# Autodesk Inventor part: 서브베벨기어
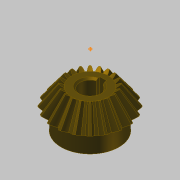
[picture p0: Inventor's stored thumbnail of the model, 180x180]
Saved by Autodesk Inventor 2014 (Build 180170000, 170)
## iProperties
Created: 2018-09
Part Number: 서브베벨기어
Material: 강철, 탄소
Document SubType Name: Modeling
Categories: <?xml version="1.0" encoding="UTF-16"?> <MemberInstance><Categories><FamilyTemplate><FamilyTemplateParameter ValueType="xs:double" Id="1" ObjectReferenceKey="da
Mass: 135.037 g
Surface Area: 63.6444 cm^2
Volume: 17.1585 cm^3
Density: 7.87 g/cm^3
Appearance: 얼룩무늬
CustomPartVersion: 1
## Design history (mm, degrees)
node "맨 위 점"
node "메쉬 평면2"
sketch "톱니 본체 스케치"
  geometry: L1 (0, 0)-(18.003, -31.331); L2 (18.003, -31.331)-(21.664, -28.891); L3 (21.664, -28.891)-(0, 0); L4 (20, -30)-(0, 0); L5 (10.813, -18.818)-(13.012, -17.352); L6 (18.003, -31.331)-(10.813, -18.818); L7 (21.664, -28.891)-(13.012, -17.352); L8 (0, -39.387)-(0, 6.564) reference; L9 (0, -30)-(21.664, -30)
  constraints: 16 end point, 4 point on line, 3 perpendicular, 2 collinear, 1 horizontal alignment, 1 vertical alignment
  dimensions: "d0" = 40 diameter of L4.start L8 (= da_de); "d1" = 36.00616 diameter of L1.end L8 (= da_dfe); "d2" = 43.3282 diameter of L2.end L8 (= da_dae); "d3" = 14.4 distance between parallel lines of L2 L5 (= da_b); "d4" = 28.8906 vertical distance of L2.end L1.start (= da_ve)
revolve "톱니 본체" sketch "톱니 본체 스케치" stored, may be unused: angle "d5" = 90 deg
node "시작점"
node "톱니 평면"
sketch "시작 스케치"
  geometry: L1 (0, -23.505)-(0, 10.645) reference; L2 (-0.834, -2.928)-(0.834, -2.928); A1 r 8.898 centre (-9.698, -3.713) between (-0.834, -2.928) and (-3.903, 3.04); A2 r 8.898 centre (9.698, -3.713) between (3.903, 3.04) and (0.834, -2.928); A3 r 27.357 centre (0, -24.037) between (3.903, 3.04) and (-3.903, 3.04); 1 further point
  constraints: 6 point on circle, 3 centre point, 3 symmetric about line, 2 end point, 1 coincident, 1 perpendicular, 1 other
  dimensions: "d7" = 8.89846 radius of A1 (= fd_rr); "d8" = 9.69794 horizontal distance of point (0, -24.037) A1.centre (= fd_x); "d9" = 20.32439 vertical distance of point (0, -24.037) A1.centre (= fd_y); "d57" = 27.35701 radius of A3 (= 0.5 x fd_dva + 0.3 x da_he); "d58" = 21.10901 distance from line of A3.centre L2 (= 0.5 x fd_dva - 1.12 x da_he)
node "끝점"
  node "끝 평면"
sketch "3D 스케치 오른쪽"
  node "Helical Curve Right" dims "d65" = 229.90621 (computed from da_dm, da_delta, da_beta), "d66" = 31.5, "d67" = 40 (= da_de), "d68" = -5.88003 (= -da_delta), "d69" = 12.16458 (computed from fd_loft, da_delta)
node "끝 평면 오른쪽"
sketch "끝 스케치 오른쪽"
  geometry: L1 (0, -22.649)-(0, 12.15) reference; L2 (-0.497, -1.72)-(0.497, -1.72); A1 r 5.299 centre (-5.775, -2.187) between (-0.497, -1.72) and (-2.324, 1.834); A2 r 5.299 centre (5.775, -2.187) between (2.324, 1.834) and (0.497, -1.72); A3 r 16.291 centre (0, -14.29) between (2.324, 1.834) and (-2.324, 1.834); 1 further point
  constraints: 6 point on circle, 3 centre point, 3 symmetric about line, 2 end point, 1 coincident, 1 perpendicular, 1 other
  dimensions: "d70" = 5.77526 horizontal distance of A3.centre A1.centre (computed from fd_x, fd_ratio); "d71" = 12.10346 vertical distance of point (0, -14.29) A1.centre (computed from fd_y, fd_ratio); "d72" = 5.29916 radius of A1 (computed from fd_rr, fd_ratio); "d73" = 12.57071 distance from line of point (0, -14.29) L2 (computed from d58, fd_ratio); "d74" = 16.29149 radius of A3 (computed from d57, fd_ratio)
feature "로프트 오른쪽" sketch "끝 스케치 오른쪽" dims "d75" = 0, "d77" = 0, "d79" = 0, "d80" = 90 deg, "d85" = 20, "d92" = 90 deg, "d93" = 90 deg, "da_teethtype" = 0 [user parameter]
sketch "3D 스케치 왼쪽"
  node "Helical Curve Left" dims "d26" = 229.90621 (computed from da_dm, da_delta, da_beta), "d27" = 12.16458 (computed from fd_loft, da_delta), "d28" = 40 (= da_de), "d29" = -5.88003 (= -da_delta)
node "끝 평면 왼쪽"
sketch "끝 스케치 왼쪽" dims "d56" = 10.82768 (derived)
  geometry: L1 (0, -35.087)-(0, 18.089) reference; L2 (-0.497, -1.716)-(0.497, -1.716); A1 r 5.299 centre (-5.775, -2.183) between (-0.497, -1.716) and (-2.324, 1.838); A2 r 5.299 centre (5.775, -2.183) between (2.324, 1.838) and (0.497, -1.716); A3 r 16.291 centre (0, -14.287) between (2.324, 1.838) and (-2.324, 1.838); 2 further points; 1 other entity
  constraints: 6 point on circle, 3 centre point, 3 symmetric about line, 2 end point, 1 coincident, 2 other
  dimensions: "d30" = 5.29916 radius of A1 (computed from fd_rr, fd_ratio); "d31" = 5.77526 horizontal distance of point (0, -14.287) A1.centre (computed from fd_x, fd_ratio); "d32" = 12.10346 vertical distance of A1.centre point (0, -14.287) (computed from fd_y, fd_ratio); "d61" = 16.29149 radius of A3 (computed from d57, fd_ratio); "d62" = 12.57071 distance from line of point (0, -14.287) L2 (computed from d58, fd_ratio)
feature "로프트 왼쪽" sketch "끝 스케치 왼쪽" dims "d35" = 0, "d37" = 0, "d39" = 0, "d40" = 90 deg, "d84" = 10, "d90" = 90 deg, "d91" = 90 deg, "da_teethtype" = 0 [user parameter]
sketch "본체 스케치"
  geometry: L1 (0, -35.038)-(0, -19.531) reference; L2 (18.003, -31.331)-(10.813, -18.818) reference; L3 (10.813, -18.818)-(0, -18.818); L4 (18.003, -31.331)-(0, -31.331)
  constraints: 4 end point, 2 perpendicular, 2 point on line
revolve "본체 고정" sketch "본체 스케치" stored, may be unused: angle "d46" = 90 deg
feature "피치 지름" dims angle "d47" = 90 deg
sketch "스케치8"
  geometry: C1 r 17 at (0, 0); 1 further point
  constraints: 1 centre point, 1 coincident
  dimensions: "d94" = 34 diameter of C1
extrude "돌출1" join sketch "스케치8" distance "d95" = 10; taper "d96" = 0 deg
sketch "스케치9"
  geometry: 1 further point
hole "구멍1" sketch "스케치9" at (0, 0) diameter "d97" = 12; stored, may be unused: countersink angle "d101" = 90 deg, drill point angle "d103" = 118 deg; dims "d98" = 6, "d99" = 4, "d100" = 2, "d102" = 8
sketch "스케치10"
  geometry: 1 further point
sketch "스케치11"
  geometry: 1 further point
sketch "스케치12"
  geometry: L1 (-2, 5.657)-(-2, 7.8); L2 (-2, 7.8)-(2, 7.8); L3 (2, 7.8)-(2, 5.657); A1 r 6 centre (0, 0) between (-2, 5.657) and (2, 5.657) reference; 1 further point
  constraints: 6 end point, 2 parallel, 2 point on circle, 1 perpendicular, 1 vertical
  dimensions: "d104" = 4 distance of L1.end L2.end; "d105" = 13.8 dimension on A1 L2
extrude "돌출2" cut sketch "스케치12" stored distance "d106" = 7; taper "d107" = 0 deg
chamfer "모따기1" distance "d108" = 1; stored, may be unused: second distance "d109" = 2, angle "d110" = 45 deg
body "Solid1"
feature "로프트" dims "d17" = 0, "d18" = 90 deg, "d19" = 0, "d20" = 90 deg, "d89" = 0, "da_teethtype" = 0 [user parameter]
pattern_circular "원형 패턴" dims angle "d22" = 360 deg, "d88" = 0, "da_teethtype" = 0 [user parameter]
pattern_circular "원형 패턴 오른쪽" dims angle "d82" = 360 deg, "da_teethtype" = 0 [user parameter]
pattern_circular "원형 패턴 왼쪽" dims angle "d42" = 360 deg, "da_teethtype" = 0 [user parameter]
sketch "끝 스케치"
  geometry: L1 (0, -15.359)-(0, 6.983) reference; L2 (-0.497, -1.72)-(0.497, -1.72); A1 r 5.299 centre (-5.775, -2.187) between (-0.497, -1.72) and (-2.324, 1.834); A2 r 5.299 centre (5.775, -2.187) between (2.324, 1.834) and (0.497, -1.72); A3 r 16.291 centre (0, -14.29) between (2.324, 1.834) and (-2.324, 1.834); 1 further point
  constraints: 6 point on circle, 3 centre point, 3 symmetric about line, 2 end point, 1 coincident, 1 other
  dimensions: "d12" = 5.29916 radius of A1 (computed from fd_rr, fd_ratio); "d15" = 5.77526 horizontal distance of A1.centre point (0, -14.29) (computed from fd_x, fd_ratio); "d16" = 12.10346 vertical distance of A1.centre point (0, -14.29) (computed from fd_y, fd_ratio); "d59" = 16.29149 radius of A3 (computed from d57, fd_ratio); "d60" = 12.57071 distance from line of A3.centre L2 (computed from d58, fd_ratio)
sketch "Sketch6"
  geometry: L1 (20, -30)-(0, 0) reference; L2 (0, -37.8)-(0, 6.3) reference
body "Srf1"
other parameters: "da_b" = 14.4 [user parameter; used in 2 equation terms], "da_de" = 40 [user parameter; used in 4 equation terms], "da_dae" = 43.3282 [user parameter; used in 2 equation terms], "da_dfe" = 36.00616 [user parameter; used in 1 equation term], "da_le" = 36.05551 [user parameter; used in 1 equation term], "da_omega" = 90 deg [user parameter; used in 1 equation term], "da_beta" = 0 [user parameter; used in 2 equation terms], "da_delta" = 5.88003 [user parameter; used in 8 equation terms], "da_alpha" = 20 deg [user parameter; used in 2 equation terms], "da_he" = 4.4 [user parameter; used in 4 equation terms], "da_ve" = 28.8906 [user parameter; used in 1 equation term], "fd_dv" = 48.07402 (computed from da_de, da_delta) [user parameter; used in 1 equation term], "fd_dva" = 52.07402 (computed from da_dae, da_delta) [user parameter; used in 3 equation terms], "fd_dvb" = 45.1748 (computed from fd_dv, da_alpha) [user parameter; used in 2 equation terms], "da_zv" = 240.37008 [user parameter; used in 1 equation term], "fd_loft" = 14.62 (= da_b + 0.05 x da_he) [user parameter; used in 4 equation terms], "fd_ratio" = 5.95514 (computed from da_le, fd_loft) [user parameter; used in 15 equation terms], "fd_rr" = 8.89846 (computed from fd_dd, fd_dvb) [user parameter; used in 6 equation terms], "fd_angle" = 0.66075 (computed from da_zv) [user parameter; used in 4 equation terms], "fd_x1" = 1.58709 (computed from da_dvw, fd_angle) [user parameter; used in 1 equation term], "fd_y1" = 23.98456 (computed from da_dvw, fd_angle) [user parameter; used in 1 equation term], "fd_x2" = 8.11084 (computed from fd_rr, fd_angle2, fd_angle) [user parameter; used in 1 equation term], "fd_y2" = 3.66016 (computed from fd_rr, fd_angle2, fd_angle) [user parameter; used in 1 equation term], "fd_x" = 9.69794 (= fd_x1 + fd_x2) [user parameter; used in 4 equation terms], "fd_y" = 20.32439 (= fd_y1 - fd_y2) [user parameter; used in 4 equation terms], "fd_angle2" = 3.57832 (computed from fd_dvb, fd_dd, da_alpha) [user parameter; used in 2 equation terms], "fd_dd" = 48.55402 (= fd_dva - 0.8 x da_he) [user parameter; used in 2 equation terms], "da_dvw" = 48.07402 [user parameter; used in 2 equation terms], "d11" = 14.62 (= fd_loft), "da_dm" = 32.01232 [user parameter; used in 2 equation terms], "da_x" = 0 [user parameter], "da_m" = 2 [user parameter], "d48" = 0, "d49" = 0, "d50" = 90 deg (= da_omega), "d51" = 9 deg (computed from da_z), "d52" = 0, "d53" = 0, "d54" = 0
